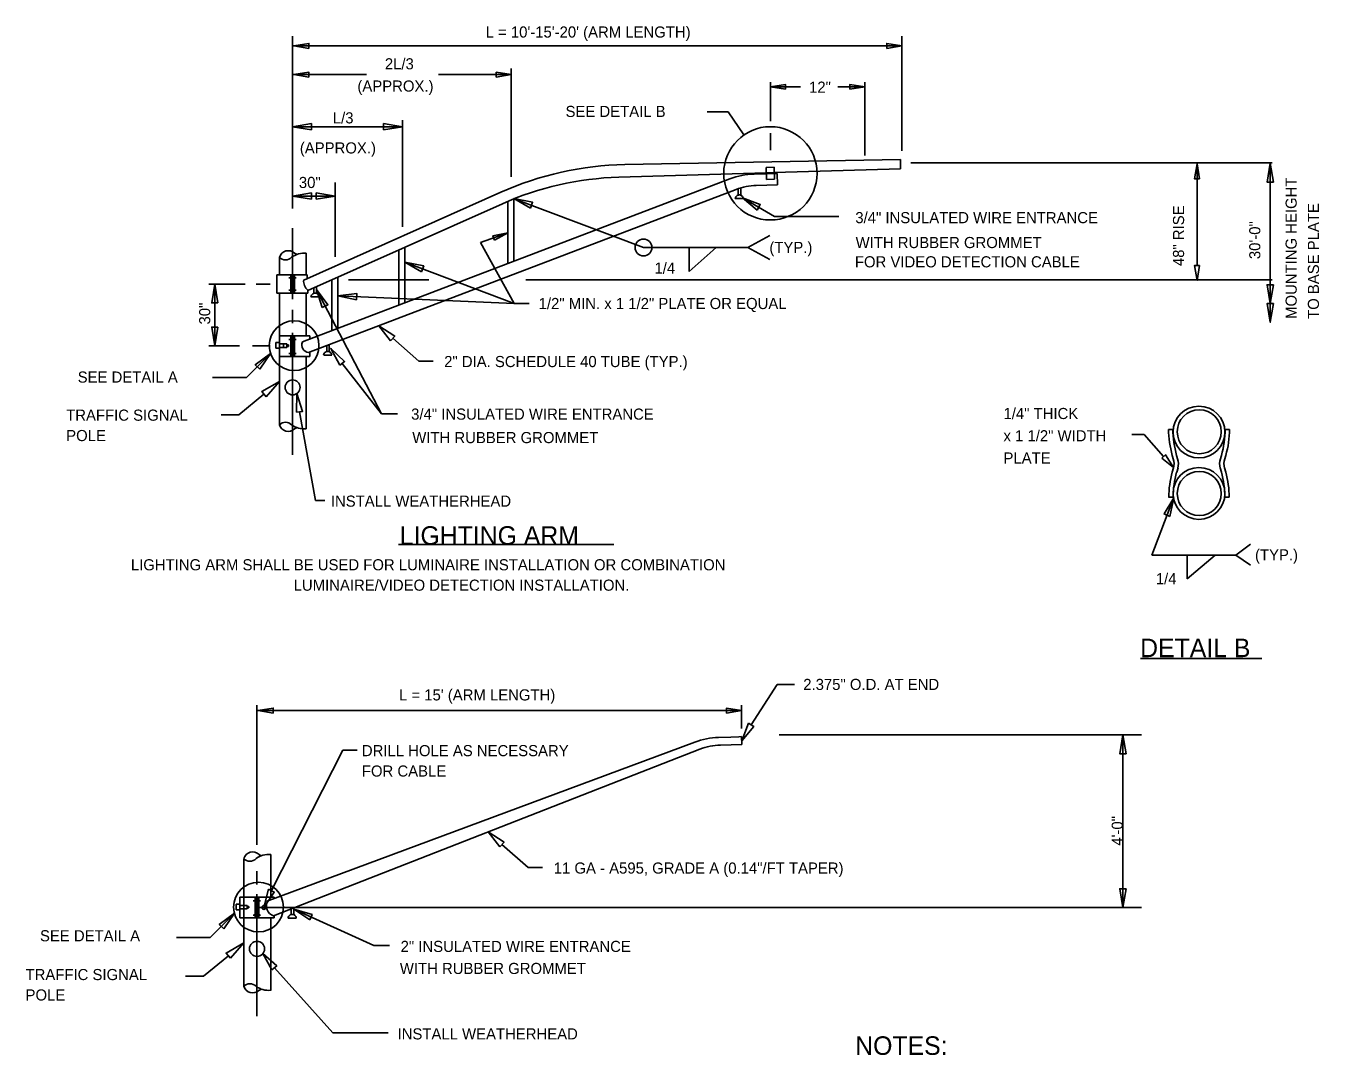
# Model space of a CAD drawing. Extents: x 12.4 to 19.6, y 6 to 16.3.
# Drawn here: x 12.41 to 19.39, y 10.73 to 16.28 of the extents above; entities that cross this region are included whole.
import ezdxf

# ---------------------------------------------------------------- set-up
doc = ezdxf.new("R2010")
doc.units = 0
for name, color, linetype in [('DETL-DIMS', 7, 'Continuous'), ('DETL-LINE', 7, 'Continuous'), ('DETL-NOTE', 7, 'Continuous'), ('DETL-TITL', 7, 'Continuous')]:
    doc.layers.add(name, color=color, linetype=linetype)

msp = doc.modelspace()

# ---------------------------------------------------------------- linework, layer by layer
at = {"layer": 'DETL-DIMS'}
for p, q in [((13.8523, 15.298), (13.8523, 16.2278)), ((17.1363, 15.608), (17.1363, 16.2278)), ((13.8523, 16.1751), (17.1363, 16.1751)), ((15.0313, 15.468), (15.0313, 16.0524)), ((13.8523, 16.0194), (14.2513, 16.0194)), ((15.0313, 16.0194), (14.6383, 16.0194)), ((16.4283, 15.768), (16.4283, 15.979)), ((16.9383, 15.584), (16.9383, 15.979)), ((16.4283, 15.954), (16.5903, 15.954)), ((16.9383, 15.954), (16.7923, 15.954)), ((14.4443, 15.199), (14.4443, 15.7732)), ((16.0873, 15.818), (16.2003, 15.818)), ((16.2003, 15.818), (16.2853, 15.694)), ((13.8523, 15.7382), (14.4443, 15.7382)), ((16.4283, 15.612), (16.4283, 15.704)), ((17.1853, 15.543), (19.1343, 15.543)), ((18.7293, 15.54), (18.7293, 14.991)), ((19.1233, 14.684), (19.1233, 15.542)), ((14.0812, 15.0372), (14.0812, 15.4369)), ((13.8523, 15.3642), (14.0812, 15.3642)), ((15.0473, 15.35), (15.7443, 15.087)), ((16.2773, 15.355), (16.4498, 15.255)), ((16.4498, 15.255), (16.7966, 15.255)), ((13.8523, 15.192), (13.8523, 14.808)), ((15.0123, 15.166), (14.8663, 15.115)), ((16.3063, 15.087), (16.4253, 15.152)), ((14.8663, 15.115), (15.0473, 14.786)), ((16.3063, 15.087), (15.7443, 15.087)), ((15.9913, 14.957), (16.1353, 15.087)), ((15.9913, 15.087), (15.9913, 14.957)), ((16.3063, 15.087), (16.4253, 15.023)), ((14.4583, 15.008), (15.0473, 14.786)), ((13.8323, 14.924), (13.8723, 14.924)), ((13.4013, 14.89), (13.5973, 14.89)), ((13.4333, 14.89), (13.4333, 14.557)), ((13.6553, 14.89), (13.7313, 14.89)), ((13.8323, 14.857), (13.8723, 14.857)), ((13.9813, 14.861), (14.3322, 14.1899)), ((14.1533, 14.913), (14.5863, 14.913)), ((15.1103, 14.913), (19.1343, 14.913)), ((14.0966, 14.827), (15.0464, 14.786)), ((15.0473, 14.786), (15.1283, 14.786)), ((13.8523, 14.751), (13.8523, 14.68)), ((13.8323, 14.592), (13.8723, 14.592)), ((13.8523, 14.628), (13.8523, 13.969)), ((14.3924, 14.5978), (14.5334, 14.4738)), ((13.4013, 14.557), (13.5663, 14.557)), ((13.7335, 14.5157), (13.6033, 14.3854)), ((13.6363, 14.557), (13.7313, 14.557)), ((13.8323, 14.515), (13.8723, 14.515)), ((14.1206, 14.4622), (14.3324, 14.1899)), ((14.6104, 14.4738), (14.5334, 14.4738)), ((13.4215, 14.3854), (13.6033, 14.3854)), ((13.6983, 14.296), (13.5633, 14.185)), ((13.5633, 14.185), (13.4673, 14.185)), ((13.8895, 14.2011), (13.9768, 13.7222)), ((14.3322, 14.1899), (14.4172, 14.1899)), ((18.443, 14.0783), (18.377, 14.0783)), ((18.548, 13.9603), (18.443, 14.0783)), ((18.602, 13.7363), (18.485, 13.4283)), ((13.9766, 13.7222), (14.0254, 13.7222)), ((18.938, 13.4283), (19.017, 13.4873)), ((18.485, 13.4283), (18.938, 13.4283)), ((18.676, 13.3003), (18.826, 13.4283)), ((18.676, 13.4283), (18.676, 13.3003)), ((18.938, 13.4283), (19.017, 13.3743)), ((16.3242, 12.5124), (16.4654, 12.7309)), ((16.4654, 12.7309), (16.5584, 12.7309)), ((13.6603, 11.8664), (13.6603, 12.6184)), ((13.6603, 12.5904), (16.2733, 12.5904)), ((16.2733, 12.4934), (16.2733, 12.6184)), ((16.4763, 12.4594), (18.4283, 12.4594)), ((18.3293, 11.5284), (18.3293, 12.4594)), ((13.7383, 11.6191), (14.1237, 12.3769)), ((14.1237, 12.3769), (14.2006, 12.3769)), ((14.9813, 11.8684), (15.1223, 11.7444)), ((13.6603, 11.7234), (13.6603, 11.6524)), ((15.1993, 11.7444), (15.1223, 11.7444)), ((13.6603, 11.6004), (13.6603, 10.9414)), ((13.6403, 11.5644), (13.6803, 11.5644)), ((13.6703, 11.5284), (18.4283, 11.5284)), ((13.8588, 11.5183), (14.2899, 11.3238)), ((13.539, 11.4974), (13.4089, 11.367)), ((13.6403, 11.4874), (13.6803, 11.4874)), ((13.2271, 11.367), (13.4089, 11.367)), ((14.2903, 11.3234), (14.3753, 11.3234)), ((13.5063, 11.2684), (13.3713, 11.1574)), ((13.3713, 11.1574), (13.2753, 11.1574)), ((13.7543, 11.2024), (14.069, 10.8519)), ((14.069, 10.8519), (14.3684, 10.8519))]:
    msp.add_line(p, q, dxfattribs=at)
for points in [[(13.9403, 16.1611), (13.9403, 16.1881), (13.8593, 16.1751)], [(17.0553, 16.1611), (17.0553, 16.1881), (17.1363, 16.1751)], [(13.9403, 16.0054), (13.9403, 16.0324), (13.8593, 16.0194)], [(14.9503, 16.0054), (14.9503, 16.0324), (15.0313, 16.0194)], [(16.5093, 15.941), (16.5093, 15.967), (16.4283, 15.954)], [(16.8573, 15.941), (16.8573, 15.967), (16.9383, 15.954)], [(13.9543, 15.7222), (13.9543, 15.7552), (13.8523, 15.7382)], [(14.3433, 15.7222), (14.3433, 15.7552), (14.4443, 15.7382)], [(18.7423, 15.457), (18.7153, 15.457), (18.7293, 15.538)], [(19.1403, 15.44), (19.1063, 15.44), (19.1233, 15.542)], [(13.9543, 15.3482), (13.9543, 15.3812), (13.8523, 15.3642)], [(13.9802, 15.3482), (13.9802, 15.3812), (14.0812, 15.3642)], [(15.1343, 15.299), (15.1463, 15.331), (15.0453, 15.351)], [(16.3563, 15.289), (16.3733, 15.319), (16.2773, 15.355)], [(14.9413, 15.126), (14.9323, 15.151), (15.0123, 15.166)], [(14.5473, 14.956), (14.5593, 14.988), (14.4583, 15.008)], [(18.7423, 14.991), (18.7153, 14.991), (18.7293, 14.91)], [(13.4503, 14.788), (13.4163, 14.788), (13.4333, 14.89)], [(14.0124, 14.7638), (14.043, 14.7785), (13.9813, 14.861)], [(19.1403, 14.886), (19.1063, 14.886), (19.1233, 14.785)], [(14.1974, 14.8054), (14.1988, 14.8395), (14.0966, 14.827)], [(19.1403, 14.785), (19.1063, 14.785), (19.1233, 14.684)], [(13.4503, 14.658), (13.4163, 14.658), (13.4333, 14.557)], [(14.3804, 14.5848), (14.4034, 14.6098), (14.3174, 14.6648)], [(13.6765, 14.4307), (13.6515, 14.4547), (13.7335, 14.5157)], [(14.1077, 14.4524), (14.1328, 14.472), (14.0583, 14.543)], [(13.7093, 14.282), (13.6863, 14.31), (13.7813, 14.365)], [(13.8727, 14.1986), (13.9063, 14.2037), (13.8762, 14.2997)], [(18.538, 13.9513), (18.558, 13.9693), (18.602, 13.9003)], [(18.582, 13.6373), (18.551, 13.6503), (18.604, 13.7373)], [(13.7483, 12.5764), (13.7483, 12.6034), (13.6673, 12.5904)], [(16.1923, 12.5764), (16.1923, 12.6034), (16.2733, 12.5904)], [(16.3103, 12.5214), (16.3383, 12.5034), (16.2743, 12.4264)], [(18.3463, 12.3574), (18.3123, 12.3574), (18.3293, 12.4594)], [(14.9693, 11.8554), (14.9923, 11.8804), (14.9063, 11.9354)], [(13.7233, 11.6264), (13.7533, 11.6114), (13.6973, 11.5284)], [(18.3463, 11.6294), (18.3123, 11.6294), (18.3293, 11.5284)], [(13.9448, 11.4613), (13.9578, 11.4903), (13.8588, 11.5183)], [(13.4823, 11.4124), (13.4573, 11.4364), (13.5393, 11.4974)], [(13.5173, 11.2544), (13.4943, 11.2824), (13.5893, 11.3374)], [(13.7413, 11.1914), (13.7673, 11.2134), (13.6913, 11.2794)]]:
    msp.add_lwpolyline(points, close=True, dxfattribs=at)
for centre, radius in [((16.4283, 15.4871), 0.2515), ((15.7442, 15.0874), 0.0453), ((13.8607, 14.558), 0.1341), ((13.6687, 11.5304), 0.1341)]:
    msp.add_circle(centre, radius, dxfattribs=at)
at = {"layer": 'DETL-LINE'}
for p, q in [((15.6443, 15.534), (17.1298, 15.5617)), ((17.1298, 15.5107), (17.1298, 15.5617)), ((16.4063, 15.49), (15.6113, 15.467)), ((16.4073, 15.485), (16.3403, 15.483)), ((16.4493, 15.52), (16.4063, 15.519)), ((16.4063, 15.519), (16.4073, 15.454)), ((16.4493, 15.491), (16.4063, 15.49)), ((16.4503, 15.486), (16.4073, 15.485)), ((16.4503, 15.456), (16.4493, 15.52)), ((17.1298, 15.5107), (16.4493, 15.491)), ((16.4653, 15.487), (16.4503, 15.486)), ((16.4653, 15.487), (16.4663, 15.425)), ((13.9053, 14.578), (16.2103, 15.457)), ((16.4663, 15.425), (16.3523, 15.422)), ((16.4073, 15.454), (16.4503, 15.456)), ((13.9123, 14.912), (14.9743, 15.385)), ((13.9383, 14.521), (16.2433, 15.4)), ((15.0453, 15.013), (15.0453, 15.35)), ((16.2393, 15.351), (16.2823, 15.351)), ((16.2553, 15.401), (16.2553, 15.371)), ((16.2553, 15.371), (16.2693, 15.371)), ((16.2693, 15.371), (16.2693, 15.407)), ((13.9343, 14.856), (14.9833, 15.323)), ((15.0123, 15.336), (15.0123, 15)), ((14.4253, 15.075), (14.4253, 14.776)), ((14.4583, 14.789), (14.4583, 15.09)), ((13.7813, 15.034), (13.7813, 14.939)), ((13.8633, 15.056), (13.8763, 15.05)), ((13.9263, 14.939), (13.9263, 15.056)), ((13.7683, 14.939), (13.9313, 14.939)), ((13.7683, 14.841), (13.7683, 14.939)), ((13.8423, 14.928), (13.8403, 14.928)), ((13.8403, 14.928), (13.8403, 14.921)), ((13.8403, 14.921), (13.8423, 14.921)), ((13.8423, 14.939), (13.8423, 14.842)), ((13.8533, 14.939), (13.8533, 14.842)), ((13.8623, 14.939), (13.8623, 14.842)), ((13.8623, 14.928), (13.8643, 14.928)), ((13.8643, 14.921), (13.8623, 14.921)), ((13.8643, 14.928), (13.8643, 14.921)), ((13.9313, 14.939), (13.9313, 14.921)), ((14.0966, 14.6509), (14.0966, 14.9282)), ((13.8423, 14.861), (13.8403, 14.861)), ((13.8403, 14.861), (13.8403, 14.854)), ((13.8403, 14.854), (13.8423, 14.854)), ((13.8623, 14.861), (13.8643, 14.861)), ((13.8643, 14.854), (13.8623, 14.854)), ((13.8643, 14.861), (13.8643, 14.854)), ((13.9343, 14.841), (13.9343, 14.856)), ((13.9673, 14.871), (13.9673, 14.841)), ((13.9813, 14.841), (13.9813, 14.877)), ((14.0636, 14.9136), (14.0636, 14.6384)), ((13.7873, 14.841), (13.7683, 14.841)), ((13.7813, 14.841), (13.7813, 14.131)), ((13.7843, 14.841), (13.9343, 14.841)), ((13.9343, 14.841), (13.7873, 14.841)), ((13.9263, 14.611), (13.9263, 14.841)), ((13.9513, 14.821), (13.9943, 14.821)), ((13.9673, 14.841), (13.9813, 14.841)), ((13.763, 14.5748), (13.7629, 14.5438)), ((13.7814, 14.5747), (13.763, 14.5748)), ((13.7812, 14.5437), (13.7814, 14.5747)), ((13.7813, 14.611), (13.7813, 14.576)), ((13.9453, 14.611), (13.7813, 14.611)), ((13.8423, 14.595), (13.8403, 14.595)), ((13.8403, 14.595), (13.8403, 14.588)), ((13.8403, 14.588), (13.8423, 14.588)), ((13.8423, 14.611), (13.8423, 14.5)), ((13.8533, 14.611), (13.8533, 14.5)), ((13.8623, 14.611), (13.8623, 14.5)), ((13.8623, 14.595), (13.8643, 14.595)), ((13.8643, 14.588), (13.8623, 14.588)), ((13.8643, 14.595), (13.8643, 14.588)), ((13.9453, 14.611), (13.9453, 14.593)), ((13.7629, 14.5438), (13.7812, 14.5437)), ((13.8033, 14.5674), (13.7813, 14.5674)), ((13.8033, 14.5484), (13.7813, 14.5484)), ((13.7813, 14.535), (13.7813, 14.513)), ((13.8033, 14.5675), (13.8032, 14.5488)), ((13.8032, 14.5488), (13.8215, 14.5487)), ((13.8216, 14.5674), (13.8033, 14.5675)), ((13.8215, 14.5487), (13.8216, 14.5674)), ((13.8215, 14.5487), (13.8216, 14.5674)), ((13.8307, 14.5543), (13.8215, 14.5543)), ((13.8216, 14.5674), (13.8216, 14.5618)), ((13.8216, 14.5618), (13.8307, 14.5618)), ((13.8307, 14.5618), (13.8307, 14.5543)), ((13.8423, 14.519), (13.8403, 14.519)), ((13.8403, 14.519), (13.8403, 14.512)), ((13.8403, 14.512), (13.8423, 14.512)), ((13.8623, 14.519), (13.8643, 14.519)), ((13.8643, 14.512), (13.8623, 14.512)), ((13.8643, 14.519), (13.8643, 14.512)), ((13.9453, 14.5), (13.9453, 14.524)), ((14.0203, 14.507), (14.0633, 14.507)), ((14.0363, 14.557), (14.0363, 14.527)), ((14.0363, 14.527), (14.0503, 14.527)), ((14.0503, 14.527), (14.0503, 14.563)), ((13.7813, 14.5), (13.9453, 14.5)), ((13.9263, 14.109), (13.9263, 14.499)), ((13.8633, 14.109), (13.8763, 14.116)), ((18.598, 14.1063), (18.575, 14.1063)), ((18.88, 14.1063), (18.904, 14.1063)), ((18.595, 13.9663), (18.602, 13.9423)), ((18.618, 13.9663), (18.625, 13.9423)), ((18.86, 13.9663), (18.853, 13.9423)), ((18.883, 13.9663), (18.876, 13.9423)), ((18.595, 13.8753), (18.602, 13.8993)), ((18.619, 13.8753), (18.626, 13.8993)), ((18.86, 13.8753), (18.853, 13.8993)), ((18.883, 13.8753), (18.876, 13.8993)), ((18.6, 13.7403), (18.575, 13.7403)), ((18.879, 13.7403), (18.902, 13.7403)), ((13.7097, 11.5597), (16.0217, 12.4201)), ((16.2156, 12.4474), (16.1486, 12.4454)), ((16.2585, 12.4484), (16.2155, 12.4474)), ((16.2735, 12.4494), (16.259, 12.4484)), ((16.2735, 12.4494), (16.2741, 12.4074)), ((13.7499, 11.484), (16.048, 12.382)), ((16.2741, 12.4074), (16.16, 12.4044)), ((13.5893, 11.7914), (13.5893, 11.1034)), ((13.6713, 11.8134), (13.6843, 11.8074)), ((13.7343, 11.5834), (13.7343, 11.8134)), ((13.7533, 11.5834), (13.5673, 11.5834)), ((13.5673, 11.4724), (13.5673, 11.5834)), ((13.5893, 11.5834), (13.5893, 11.5484)), ((13.6503, 11.5834), (13.6503, 11.4724)), ((13.6613, 11.5834), (13.6613, 11.4724)), ((13.6703, 11.5834), (13.6703, 11.4724)), ((13.7533, 11.5834), (13.7533, 11.5759)), ((13.549, 11.5468), (13.5489, 11.5158)), ((13.5489, 11.5158), (13.5672, 11.5157)), ((13.5673, 11.5467), (13.549, 11.5468)), ((13.5672, 11.5157), (13.5673, 11.5467)), ((13.5893, 11.5394), (13.5673, 11.5394)), ((13.5893, 11.5204), (13.5673, 11.5204)), ((13.5892, 11.5395), (13.5891, 11.5208)), ((13.5891, 11.5208), (13.6075, 11.5207)), ((13.6076, 11.5394), (13.5892, 11.5395)), ((13.5893, 11.5074), (13.5893, 11.4854)), ((13.6075, 11.5207), (13.6076, 11.5394)), ((13.6075, 11.5207), (13.6076, 11.5394)), ((13.6076, 11.5394), (13.6075, 11.5338)), ((13.6075, 11.5338), (13.6167, 11.5338)), ((13.6167, 11.5263), (13.6075, 11.5263)), ((13.6167, 11.5338), (13.6167, 11.5263)), ((13.6503, 11.5674), (13.6483, 11.5674)), ((13.6483, 11.5674), (13.6483, 11.5604)), ((13.6483, 11.5604), (13.6503, 11.5604)), ((13.6703, 11.5674), (13.6723, 11.5674)), ((13.6723, 11.5604), (13.6703, 11.5604)), ((13.6723, 11.5674), (13.6723, 11.5604)), ((13.8448, 11.5211), (13.8448, 11.4911)), ((13.8588, 11.4911), (13.8588, 11.5266)), ((13.5673, 11.4724), (13.7533, 11.4724)), ((13.6503, 11.4914), (13.6483, 11.4914)), ((13.6483, 11.4914), (13.6483, 11.4844)), ((13.6483, 11.4844), (13.6503, 11.4844)), ((13.6703, 11.4914), (13.6723, 11.4914)), ((13.6723, 11.4844), (13.6703, 11.4844)), ((13.6723, 11.4914), (13.6723, 11.4844)), ((13.7343, 11.0814), (13.7343, 11.4714)), ((13.7533, 11.4724), (13.7533, 11.4854)), ((13.8288, 11.4711), (13.8718, 11.4711)), ((13.8448, 11.4911), (13.8588, 11.4911)), ((13.6713, 11.0814), (13.6843, 11.0884))]:
    msp.add_line(p, q, dxfattribs=at)
for centre, radius in [((13.8527, 14.3328), 0.0405), ((18.739, 14.092), 0.1397), ((18.7406, 14.0937), 0.1188), ((18.739, 13.7609), 0.1397), ((18.7406, 13.7606), 0.1188), ((13.6973, 11.5284), 0.0106), ((13.6607, 11.3052), 0.0405)]:
    msp.add_circle(centre, radius, dxfattribs=at)
for centre, radius, start, end in [((15.676, 13.8103), 1.7242, 91.06172, 114.0049), ((16.3518, 15.0854), 0.3978, 91.67734, 110.87649), ((15.6602, 13.8032), 1.664, 91.68232, 114.00496), ((16.3622, 15.0893), 0.3328, 91.67078, 110.87395), ((16.2603, 15.3477), 0.0221, 119.85769, 172.43275), ((16.2562, 15.3607), 0.00921, 81.01358, 137.9786), ((16.267, 15.3622), 0.0077, 19.6688, 100.76845), ((16.2603, 15.3477), 0.0221, 7.56725, 50.79453), ((13.8291, 15.021), 0.0491, 45.37513, 164.37623), ((13.8145, 15.0662), 0.0457, 224.24269, 315.75731), ((13.916, 14.9391), 0.1174, 84.97074, 125.81411), ((13.9784, 14.9062), 0.0664, 174.68579, 228.71687), ((13.9728, 14.8184), 0.0221, 119.85769, 172.43275), ((13.9686, 14.8314), 0.00921, 81.01358, 137.9786), ((13.9795, 14.8329), 0.0077, 19.6688, 100.76845), ((13.9728, 14.8184), 0.0221, 7.56725, 50.79453), ((13.9445, 14.5624), 0.042, 158.53064, 261.77475), ((14.0417, 14.5045), 0.0221, 119.85769, 172.43275), ((14.0375, 14.5175), 0.00921, 81.01358, 137.9786), ((14.0484, 14.519), 0.0077, 19.6688, 100.76845), ((14.0417, 14.5045), 0.0221, 7.56725, 50.79453), ((13.8145, 14.0991), 0.0457, 44.24269, 135.75731), ((13.8291, 14.1442), 0.0491, 195.62377, 314.62487), ((13.916, 14.2262), 0.1174, 234.18589, 275.02926), ((19.0906, 14.1104), 0.5159, 180.41549, 196.19473), ((19.114, 14.1104), 0.5159, 180.41549, 196.19473), ((18.3645, 14.1104), 0.5159, 343.80527, 359.58451), ((18.3879, 14.1104), 0.5159, 343.80527, 359.58451), ((18.5195, 13.9204), 0.0854, 344.90697, 18.08153), ((18.5428, 13.9204), 0.0854, 344.90697, 18.08153), ((18.9356, 13.9204), 0.0854, 161.91847, 195.09303), ((18.959, 13.9204), 0.0854, 161.91847, 195.09303), ((19.0921, 13.7365), 0.5159, 164.35627, 179.58451), ((19.1155, 13.7365), 0.5159, 164.35627, 179.58451), ((18.3629, 13.7365), 0.5159, 0.41549, 15.64373), ((18.3863, 13.7365), 0.5159, 0.41549, 15.64373), ((16.1598, 12.0578), 0.3878, 91.67734, 110.87649), ((16.1702, 12.0617), 0.3428, 91.67078, 110.87395), ((13.6371, 11.7784), 0.0491, 45.37513, 164.37623), ((13.6225, 11.8236), 0.0457, 224.24269, 315.75731), ((13.724, 11.6965), 0.1174, 84.97074, 125.81411), ((13.7657, 11.5365), 0.0548, 149.9504, 253.19452), ((13.8501, 11.4686), 0.0221, 119.85769, 172.43275), ((13.846, 11.4816), 0.00921, 81.01358, 137.9786), ((13.8569, 11.4831), 0.0077, 19.6688, 100.76845), ((13.8501, 11.4686), 0.0221, 7.56725, 50.79453), ((13.6225, 11.0715), 0.0457, 44.24269, 135.75731), ((13.6371, 11.1166), 0.0491, 195.62377, 314.62487), ((13.724, 11.1986), 0.1174, 234.18589, 275.02926)]:
    msp.add_arc(centre, radius, start, end, dxfattribs=at)
at = {"layer": 'DETL-TITL'}
for p, q in [((14.4234, 13.4857), (15.5852, 13.4857)), ((18.4236, 12.8711), (19.0781, 12.8711))]:
    msp.add_line(p, q, dxfattribs=at)

# ---------------------------------------------------------------- texts
at = {"layer": 'DETL-NOTE'}
for s, height, p in [("L = 10'-15'-20' (ARM LENGTH)", 0.06, (14.8933, 16.2193)), ('2L/3', 0.06, (14.3499, 16.048)), ('(APPROX.)', 0.06, (14.202, 15.928)), ('12"', 0.06, (16.6368, 15.922)), ('SEE DETAIL B', 0.06, (15.3241, 15.7911)), ('L/3', 0.06, (14.0695, 15.7563)), ('(APPROX.)', 0.06, (13.8916, 15.5943)), ('30"', 0.06, (13.8864, 15.408)), ('3/4" INSULATED WIRE ENTRANCE', 0.06, (16.8863, 15.2183)), ('WITH RUBBER GROMMET', 0.06, (16.888, 15.0841)), ('(TYP.)', 0.06, (16.4231, 15.0578)), ('1/4', 0.06, (15.8033, 14.9461)), ('FOR VIDEO DETECTION CABLE', 0.06, (16.884, 14.9801)), ('1/2" MIN. x 1 1/2" PLATE OR EQUAL', 0.06, (15.1789, 14.7553)), ('2" DIA. SCHEDULE 40 TUBE (TYP.)', 0.06, (14.6696, 14.4423)), ('SEE DETAIL A', 0.06, (12.6938, 14.3586)), ('1/4" THICK ', 0.06, (17.6851, 14.1621)), ('TRAFFIC SIGNAL', 0.06, (12.6318, 14.1532)), ('3/4" INSULATED WIRE ENTRANCE', 0.06, (14.4916, 14.1589)), ('POLE', 0.06, (12.6318, 14.0432)), ('WITH RUBBER GROMMET', 0.06, (14.4977, 14.0323)), ('x 1 1/2" WIDTH', 0.06, (17.6851, 14.0421)), ('PLATE', 0.06, (17.6851, 13.9221)), ('INSTALL WEATHERHEAD', 0.06, (14.0587, 13.6896)), ('(TYP.)', 0.06, (19.0411, 13.3999)), ('LIGHTING ARM SHALL BE USED FOR LUMINAIRE INSTALLATION OR COMBINATION', 0.06, (12.9807, 13.3464)), ('1/4', 0.06, (18.5063, 13.2711)), ('LUMINAIRE/VIDEO DETECTION INSTALLATION.', 0.06, (13.8582, 13.2364)), ('2.375" O.D. AT END', 0.06, (16.6055, 12.7012)), ("L = 15' (ARM LENGTH)", 0.06, (14.4263, 12.6446)), ('DRILL HOLE AS NECESSARY', 0.06, (14.226, 12.3441)), ('FOR CABLE', 0.06, (14.226, 12.2341)), ('11 GA - A595, GRADE A (0.14"/FT TAPER)', 0.06, (15.2603, 11.7109)), ('SEE DETAIL A', 0.06, (12.4906, 11.3458)), ('2" INSULATED WIRE ENTRANCE', 0.06, (14.4348, 11.2884)), ('WITH RUBBER GROMMET', 0.06, (14.4307, 11.1695)), ('TRAFFIC SIGNAL', 0.06, (12.4127, 11.1366)), ('POLE', 0.06, (12.4127, 11.0266)), ('INSTALL WEATHERHEAD', 0.06, (14.4184, 10.8167)), ('NOTES:', 0.1, (16.8857, 10.7334))]:
    msp.add_text(s, height=height, dxfattribs=at).set_placement(p)
for s, p in [('MOUNTING HEIGHT', (19.266, 14.7022)), ('48" RISE', (18.6588, 14.987)), ('TO BASE PLATE', (19.386, 14.7022)), ('30\'-0"', (19.0699, 15.0246)), ('30"', (13.4085, 14.6721)), ('4\'-0"', (18.3283, 11.8616))]:
    msp.add_text(s, height=0.06, rotation=90, dxfattribs=at).set_placement(p)
at = {"layer": 'DETL-TITL'}
for s, p in [('LIGHTING ARM', (14.4304, 13.4842)), ('DETAIL B', (18.4218, 12.8781))]:
    msp.add_text(s, height=0.1, dxfattribs=at).set_placement(p)

doc.saveas('drawing.dxf')
